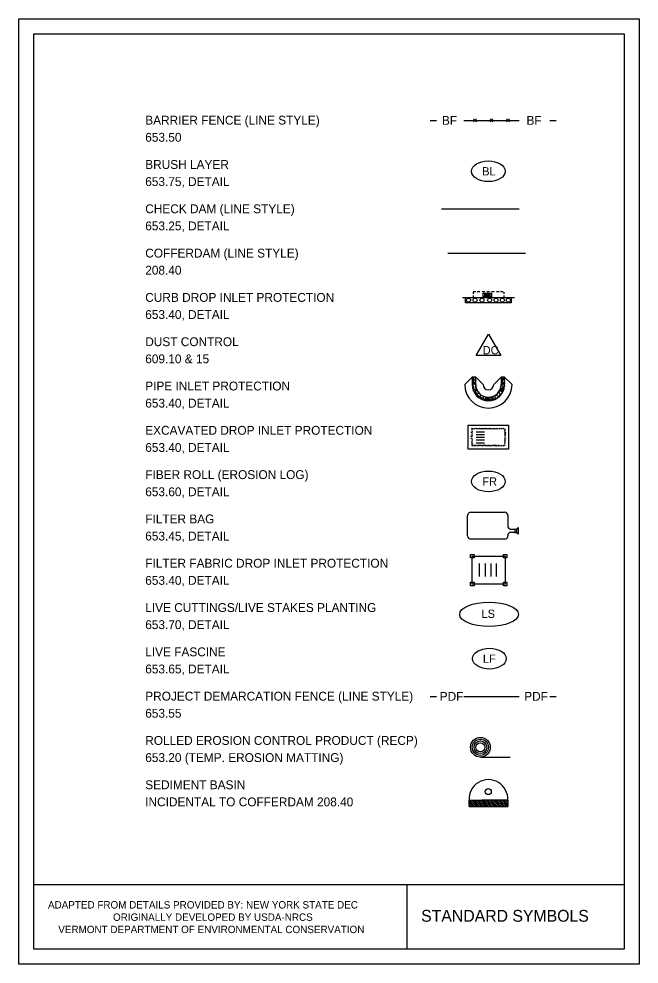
# Model space of a CAD drawing. Extents: x 0 to 556, y -320 to 0.
# Drawn here: x 0 to 210, y -320 to 0 of the extents above; entities that cross this region are included whole.
import ezdxf

# ---------------------------------------------------------------- set-up
doc = ezdxf.new("R2010")
doc.units = 0
for name, color, linetype in [('Default', 7, 'Continuous'), ('Level 6', 7, 'Continuous'), ('NBC1', 7, 'Continuous'), ('NBL1', 7, 'Continuous'), ('NBL1_T', 7, 'Continuous'), ('ODIM_T', 7, 'Continuous')]:
    doc.layers.add(name, color=color, linetype=linetype)

# ---------------------------------------------------------------- blocks, each defined once
blk = doc.blocks.new('UNITSQUARE')
at = {"layer": 'Default'}
for p, q in [((0.001, 0.001), (0, 0.001)), ((0, 0.001), (0, 0)), ((0, 0), (0.001, 0)), ((0.001, 0), (0.001, 0.001))]:
    blk.add_line(p, q, dxfattribs=at)
blk = doc.blocks.new('A$C052A225E')
at = {"layer": 'Default'}
for p, q in [((0.00443, 0.00472), (0.00552, 0.00472)), ((0.00445, 0.00437), (0.00445, 0.00368)), ((0.0061, 0.00472), (0.00718, 0.00472)), ((0.00814, 0.00472), (0.00922, 0.00472)), ((0.0101, 0.00472), (0.01119, 0.00472)), ((0.01207, 0.00472), (0.01315, 0.00472)), ((0.01418, 0.00472), (0.01527, 0.00472)), ((0.01584, 0.00472), (0.01693, 0.00472)), ((0.01723, 0.00435), (0.01723, 0.00366)), ((0, 0.00221), (0.0216, 0.00221)), ((0.00128, 0), (0.00128, 0.00221)), ((0.00445, 0.00303), (0.00445, 0.00234)), ((0.01723, 0.00299), (0.01723, 0.0023)), ((0.02025, 0.00221), (0.02025, 0)), ((0.02025, 0), (0.00128, 0))]:
    blk.add_line(p, q, dxfattribs=at)
for centre in [(0.00249, 0.00107), (0.0052, 0.00107), (0.00813, 0.00107), (0.01126, 0.00107), (0.01397, 0.00107), (0.01654, 0.00107), (0.01904, 0.00107)]:
    blk.add_circle(centre, 0.000856, dxfattribs=at)
for p, xscale, yscale in [((0.00864, 0.00399), 3.35095312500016, -1.4972343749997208), ((0.00927, 0.00356), 2.1389062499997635, -0.7842656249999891), ((0.0097, 0.00328), 1.3546406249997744, -0.21389062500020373)]:
    blk.add_blockref('UNITSQUARE', p, dxfattribs=dict(at, xscale=xscale, yscale=yscale))

msp = doc.modelspace()

# ---------------------------------------------------------------- linework, layer by layer
at = {"layer": 'Level 6'}
for p, q in [((139.29, -34.36), (141.43, -34.36)), ((150.71, -34.36), (169.34, -34.36)), ((153.94, -33.86), (154.94, -34.86)), ((153.94, -34.86), (154.94, -33.86)), ((159.53, -33.86), (160.53, -34.86)), ((159.53, -34.86), (160.53, -33.86)), ((165.11, -33.86), (166.11, -34.86)), ((165.11, -34.86), (166.11, -33.86)), ((179.72, -34.36), (181.87, -34.36)), ((143.08, -64.29), (169.44, -64.29)), ((145.19, -79.29), (171.56, -79.29)), ((150.97, -123.78), (153.47, -121.28)), ((154.67, -121.28), (153.47, -121.28)), ((153.47, -121.28), (153.47, -123.78)), ((154.08, -121.78), (154.08, -121.28)), ((154.61, -121.28), (154.63, -121.48)), ((154.63, -121.48), (154.67, -121.52)), ((154.67, -121.28), (157.17, -123.78)), ((154.67, -123.78), (154.67, -121.28)), ((160.77, -123.78), (163.27, -121.28)), ((164.47, -121.28), (163.27, -121.28)), ((163.27, -121.28), (163.27, -123.78)), ((163.92, -121.78), (163.92, -121.28)), ((164.45, -121.28), (164.47, -121.48)), ((164.47, -121.28), (166.97, -123.78)), ((164.47, -123.78), (164.47, -121.28)), ((164.47, -121.48), (164.47, -121.48)), ((153.47, -121.76), (154.08, -121.78)), ((153.47, -122.17), (153.53, -122.13)), ((153.47, -122.56), (153.76, -122.53)), ((153.47, -122.81), (153.88, -123.18)), ((153.47, -123.79), (153.88, -123.81)), ((153.48, -123.96), (153.53, -123.96)), ((153.53, -122.13), (153.76, -122.53)), ((153.53, -123.96), (154.08, -124.43)), ((153.88, -123.81), (153.88, -123.18)), ((153.94, -123.08), (153.96, -122.31)), ((153.94, -123.08), (154.57, -123.08)), ((153.96, -122.31), (154.31, -121.96)), ((154.08, -125.06), (154.08, -124.43)), ((154.14, -123.55), (154.29, -123.29)), ((154.14, -123.55), (154.37, -123.81)), ((154.29, -123.29), (154.59, -123.41)), ((154.31, -121.95), (154.57, -123.08)), ((154.37, -123.81), (154.61, -123.59)), ((154.55, -124.07), (154.68, -124.06)), ((154.55, -124.08), (154.63, -124.76)), ((154.57, -122.07), (154.67, -121.98)), ((154.57, -122.07), (154.67, -122.37)), ((154.59, -123.41), (154.61, -123.59)), ((154.63, -124.76), (154.83, -124.95)), ((154.67, -122.37), (154.67, -122.37)), ((163.27, -121.76), (163.92, -121.78)), ((163.27, -122.2), (163.37, -122.13)), ((163.27, -122.51), (163.31, -122.57)), ((163.27, -122.77), (163.72, -123.18)), ((163.27, -123.79), (163.72, -123.81)), ((163.27, -123.97), (163.37, -123.96)), ((163.31, -122.57), (163.6, -122.53)), ((163.37, -122.13), (163.6, -122.53)), ((163.37, -123.96), (163.92, -124.43)), ((163.72, -123.81), (163.72, -123.18)), ((163.78, -123.08), (163.8, -122.31)), ((163.78, -123.08), (164.41, -123.08)), ((163.8, -122.31), (164.16, -121.96)), ((163.92, -125.06), (163.92, -124.43)), ((163.98, -123.55), (164.14, -123.29)), ((163.98, -123.55), (164.21, -123.81)), ((164.14, -123.29), (164.43, -123.41)), ((164.16, -121.96), (164.41, -123.08)), ((164.21, -123.81), (164.45, -123.59)), ((164.39, -124.07), (164.47, -124.07)), ((164.39, -124.07), (164.43, -124.44)), ((164.41, -122.07), (164.47, -122.02)), ((164.41, -122.07), (164.47, -122.26)), ((164.43, -123.41), (164.45, -123.59)), ((153.62, -125.05), (154.08, -125.06)), ((153.95, -126.02), (153.96, -125.59)), ((153.96, -125.59), (154.31, -125.24)), ((154.11, -126.36), (154.57, -126.36)), ((154.26, -126.62), (154.29, -126.57)), ((154.29, -126.57), (154.59, -126.69)), ((154.31, -125.24), (154.57, -126.36)), ((154.49, -126.97), (154.61, -126.87)), ((154.57, -125.35), (154.71, -125.24)), ((154.57, -125.35), (154.67, -125.65)), ((154.59, -126.69), (154.61, -126.87)), ((154.67, -125.65), (154.96, -125.63)), ((154.69, -126.4), (154.81, -125.91)), ((154.69, -126.4), (155.04, -127.07)), ((154.71, -125.24), (154.94, -125.28)), ((154.77, -127.33), (155.2, -127.3)), ((154.81, -125.91), (155.11, -125.67)), ((154.96, -125.63), (155, -125.43)), ((155.04, -127.07), (155.59, -126.75)), ((155.2, -127.3), (155.75, -127.77)), ((155.59, -126.75), (155.64, -126.5)), ((155.75, -127.77), (155.76, -128.25)), ((156.14, -127.3), (156.45, -127.27)), ((156.14, -127.3), (156.24, -127.99)), ((156.24, -127.99), (156.61, -128.32)), ((157.36, -128.34), (157.36, -127.77)), ((157.9, -127.95), (157.91, -128.04)), ((160.64, -128.34), (160.64, -127.75)), ((161.13, -127.5), (161.19, -128.04)), ((161.41, -127.33), (161.76, -127.3)), ((161.76, -127.3), (162.31, -127.77)), ((161.99, -126.84), (162.15, -126.75)), ((162.15, -126.75), (162.17, -126.66)), ((162.31, -127.77), (162.32, -128.15)), ((162.53, -126.21), (162.6, -126.71)), ((162.6, -126.71), (162.97, -127.07)), ((162.64, -126.03), (163.17, -125.96)), ((162.7, -127.3), (163.24, -127.25)), ((162.7, -127.3), (162.77, -127.77)), ((162.89, -125.57), (162.97, -125.49)), ((162.94, -125.43), (162.97, -125.49)), ((162.97, -127.07), (163.38, -127.08)), ((163.1, -124.98), (163.17, -125.04)), ((163.17, -125.04), (163.92, -125.06)), ((163.17, -125.96), (163.72, -126.46)), ((163.21, -125.53), (163.37, -125.41)), ((163.21, -125.71), (163.21, -125.53)), ((163.21, -125.71), (163.31, -125.85)), ((163.31, -125.85), (163.6, -125.81)), ((163.37, -125.41), (163.6, -125.81)), ((163.72, -126.56), (163.72, -126.46)), ((163.78, -126.36), (163.8, -125.59)), ((163.78, -126.36), (163.83, -126.36)), ((163.8, -125.59), (164.16, -125.24)), ((164.16, -125.24), (164.21, -125.47)), ((156.17, -128.51), (156.26, -128.48)), ((156.26, -128.48), (156.32, -128.6)), ((156.61, -128.32), (157.36, -128.34)), ((156.69, -128.78), (156.81, -128.69)), ((156.81, -128.69), (156.92, -128.89)), ((157.24, -128.87), (157.59, -128.52)), ((157.24, -129), (157.24, -128.87)), ((157.59, -128.52), (157.74, -129.14)), ((157.85, -128.63), (157.99, -128.52)), ((157.85, -128.63), (157.95, -128.93)), ((157.91, -128.04), (158.28, -128.38)), ((157.95, -128.93), (158.24, -128.91)), ((157.99, -128.52), (158.3, -128.58)), ((158.08, -129.21), (158.09, -129.19)), ((158.09, -129.19), (158.62, -128.77)), ((158.24, -128.91), (158.3, -128.58)), ((158.28, -128.38), (159.05, -128.42)), ((158.62, -128.77), (159, -129.28)), ((159.04, -128.08), (159.05, -128.42)), ((159.2, -128.77), (159.26, -128.6)), ((159.2, -128.77), (159.3, -128.93)), ((159.26, -128.6), (159.54, -128.48)), ((159.3, -128.93), (159.46, -128.97)), ((159.46, -128.97), (159.69, -128.77)), ((159.54, -128.48), (159.69, -128.77)), ((159.58, -128.04), (159.89, -128.32)), ((159.89, -128.32), (160.64, -128.34)), ((159.93, -128.81), (160.09, -128.69)), ((159.93, -128.99), (159.93, -128.81)), ((159.93, -128.99), (160.03, -129.13)), ((160.03, -129.13), (160.32, -129.09)), ((160.09, -128.69), (160.32, -129.09)), ((160.52, -128.87), (160.88, -128.52)), ((160.52, -129.06), (160.52, -128.87)), ((160.88, -128.52), (160.96, -128.91)), ((161.13, -128.63), (161.27, -128.52)), ((161.13, -128.63), (161.19, -128.82)), ((161.19, -128.04), (161.56, -128.38)), ((161.27, -128.52), (161.58, -128.58)), ((161.56, -128.38), (161.96, -128.4)), ((161.57, -128.63), (161.58, -128.58)), ((153.57, -140.17), (153.03, -139.99)), ((153.57, -138.93), (153.21, -138.57)), ((153.57, -139.28), (153.21, -139.11)), ((153.57, -139.64), (153.21, -139.82)), ((153.57, -140.52), (153.21, -140.7)), ((153.74, -138.93), (153.74, -138.57)), ((154.1, -138.93), (154.28, -138.57)), ((154.63, -138.93), (154.45, -138.57)), ((154.81, -139.82), (157.64, -139.82)), ((154.81, -140.7), (157.64, -140.7)), ((154.98, -138.93), (155.16, -138.57)), ((155.52, -138.93), (155.52, -138.57)), ((156.05, -138.93), (155.87, -138.57)), ((156.4, -138.93), (156.4, -138.57)), ((156.76, -138.93), (156.93, -138.57)), ((157.29, -138.93), (157.11, -138.57)), ((157.64, -138.93), (157.47, -138.57)), ((158, -138.93), (158, -138.57)), ((158.35, -138.93), (158.53, -138.57)), ((158.88, -138.93), (158.88, -138.57)), ((159.24, -138.93), (159.42, -138.57)), ((159.59, -138.93), (159.77, -138.57)), ((160.13, -138.93), (160.3, -138.57)), ((160.66, -138.93), (160.48, -138.57)), ((161.01, -138.93), (161.01, -138.57)), ((161.37, -138.93), (161.54, -138.57)), ((161.72, -138.93), (161.9, -138.57)), ((162.25, -138.93), (162.43, -138.57)), ((162.78, -138.93), (162.96, -138.57)), ((163.32, -138.93), (163.49, -138.57)), ((163.85, -138.93), (164.03, -138.57)), ((164.2, -138.93), (164.03, -138.57)), ((164.38, -138.93), (164.56, -138.75)), ((164.38, -139.28), (164.73, -138.93)), ((164.38, -139.64), (164.73, -139.28)), ((164.38, -139.82), (164.91, -140.17)), ((164.38, -140.35), (164.91, -140.35)), ((164.56, -140.88), (164.91, -140.52)), ((153.57, -141.06), (153.03, -141.23)), ((153.57, -141.59), (153.03, -141.41)), ((153.57, -142.12), (153.03, -141.94)), ((153.57, -142.47), (153.21, -142.65)), ((153.57, -142.83), (153.21, -143.18)), ((153.57, -143.54), (153.21, -143.72)), ((153.57, -143.89), (153.21, -144.07)), ((154.81, -141.59), (157.64, -141.59)), ((154.81, -142.47), (157.64, -142.47)), ((154.81, -143.54), (157.64, -143.54)), ((164.38, -141.23), (164.91, -141.06)), ((164.38, -141.77), (164.91, -141.94)), ((164.38, -142.3), (164.73, -142.12)), ((164.38, -142.83), (164.73, -142.47)), ((164.38, -143.01), (164.73, -143.18)), ((164.38, -143.54), (164.56, -143.36)), ((164.38, -143.89), (164.73, -143.72)), ((153.57, -144.25), (153.21, -144.6)), ((153.74, -144.25), (153.74, -144.6)), ((154.1, -144.25), (154.28, -144.6)), ((154.63, -144.25), (154.45, -144.6)), ((154.98, -144.25), (155.16, -144.6)), ((155.52, -144.25), (155.52, -144.6)), ((156.05, -144.25), (155.87, -144.6)), ((156.4, -144.25), (156.4, -144.6)), ((156.76, -144.25), (156.93, -144.6)), ((157.29, -144.25), (157.11, -144.6)), ((157.64, -144.25), (157.47, -144.6)), ((158, -144.25), (158, -144.6)), ((158.35, -144.25), (158.53, -144.6)), ((158.88, -144.25), (158.88, -144.6)), ((159.24, -144.25), (159.42, -144.6)), ((159.59, -144.25), (159.77, -144.6)), ((160.13, -144.25), (160.3, -144.6)), ((160.66, -144.25), (160.48, -144.6)), ((161.01, -144.25), (161.01, -144.6)), ((161.37, -144.25), (161.54, -144.6)), ((161.72, -144.25), (161.9, -144.6)), ((162.25, -144.25), (162.43, -144.6)), ((162.78, -144.25), (162.96, -144.6)), ((163.32, -144.25), (163.49, -144.6)), ((163.85, -144.25), (164.03, -144.6)), ((164.2, -144.25), (164.03, -144.6)), ((164.38, -144.25), (164.56, -144.42)), ((165.6, -168.18), (165.6, -171.87)), ((166.45, -172.73), (168.44, -172.73)), ((167.87, -172.73), (167.87, -173.86)), ((167.87, -172.73), (168.44, -172.73)), ((168.44, -172.73), (169.01, -172.16)), ((168.44, -172.73), (168.44, -173.86)), ((169.01, -172.16), (169.01, -174.43)), ((168.44, -173.86), (166.45, -173.86)), ((167.87, -173.86), (168.44, -173.86)), ((169.01, -174.43), (168.44, -173.86)), ((155.83, -184.39), (155.83, -188.78)), ((157.91, -184.39), (157.91, -188.78)), ((159.76, -184.39), (159.76, -188.78)), ((161.61, -184.39), (161.61, -188.78)), ((139.29, -229.36), (141.43, -229.36)), ((150.71, -229.36), (169.34, -229.36)), ((179.72, -229.36), (181.87, -229.36)), ((156.26, -249.93), (166.3, -249.93)), ((152.42, -264.52), (156.79, -264.52)), ((152.42, -266.7), (152.42, -264.52)), ((152.42, -264.95), (154.17, -266.7)), ((153.56, -266.7), (152.42, -265.56)), ((154.78, -266.7), (152.6, -264.52)), ((153.21, -264.52), (155.39, -266.7)), ((156, -266.7), (153.82, -264.52)), ((154.43, -264.52), (156.61, -266.7)), ((157.22, -266.7), (155.04, -264.52)), ((155.65, -264.52), (157.84, -266.7)), ((158.45, -266.7), (156.26, -264.52)), ((161.16, -264.52), (156.79, -264.52)), ((156.87, -264.52), (159.06, -266.7)), ((159.67, -266.7), (157.48, -264.52)), ((158.1, -264.52), (160.28, -266.7)), ((160.89, -266.7), (158.71, -264.52)), ((159.32, -264.52), (161.5, -266.7)), ((162.11, -266.7), (159.93, -264.52)), ((160.54, -264.52), (162.72, -266.7)), ((163.34, -266.7), (161.15, -264.52)), ((165.53, -264.52), (161.16, -264.52)), ((161.76, -264.52), (163.95, -266.7)), ((164.56, -266.7), (162.37, -264.52)), ((162.98, -264.52), (165.17, -266.7)), ((165.53, -266.45), (163.59, -264.52)), ((164.21, -264.52), (165.53, -265.84)), ((165.53, -265.23), (164.82, -264.52)), ((165.43, -264.52), (165.53, -264.62)), ((165.53, -264.52), (165.53, -266.7)), ((152.42, -266.17), (152.95, -266.7)), ((152.42, -266.7), (156.79, -266.7)), ((156.79, -266.7), (161.16, -266.7)), ((161.16, -266.7), (165.53, -266.7))]:
    msp.add_line(p, q, dxfattribs=at)
for points in [[(154.82, -113.99), (158.97, -106.79), (163.13, -113.99)], [(152.15, -137.51), (165.8, -137.51), (165.8, -145.67), (152.15, -145.67)], [(152.95, -181.28), (154.1, -181.28), (154.1, -182.43), (152.95, -182.43)], [(153.52, -181.85), (164.61, -181.85), (164.61, -191.32), (153.52, -191.32)], [(164.03, -181.28), (165.18, -181.28), (165.18, -182.43), (164.03, -182.43)], [(152.95, -190.75), (154.1, -190.75), (154.1, -191.9), (152.95, -191.9)], [(164.03, -190.75), (165.18, -190.75), (165.18, -191.9), (164.03, -191.9)]]:
    msp.add_lwpolyline(points, close=True, dxfattribs=at)
for points in [[(151.95, -175), (151.95, -168.18)], [(153.08, -167.04), (164.46, -167.04)], [(165.6, -174.72), (165.6, -175)], [(164.46, -176.14), (153.08, -176.14)]]:
    msp.add_lwpolyline(points, dxfattribs=at)
for centre, radius in [((156.26, -246.59), 3.34), ((156.26, -246.59), 2.74), ((156.26, -246.59), 2.14), ((156.26, -246.59), 1.54), ((158.93, -261.59), 1.02)]:
    msp.add_circle(centre, radius, dxfattribs=at)
for centre, radius, start, end in [((158.97, -123.78), 8, 180, 0), ((158.97, -123.78), 5.5, 180, 0), ((158.97, -123.78), 4.3, 180, 0), ((158.97, -123.78), 1.8, 180, 0), ((153.08, -168.18), 1.14, 90, 180), ((164.46, -168.18), 1.14, 0, 90), ((166.45, -171.87), 0.853, 180, 270), ((153.08, -175), 1.14, 180, 270), ((164.46, -175), 1.14, 270, 0), ((166.45, -174.72), 0.853, 90, 180), ((158.97, -264.12), 6.57, 356.5251, 183.4749)]:
    msp.add_arc(centre, radius, start, end, dxfattribs=at)
for centre, major_axis, ratio in [((158.97, -51.59), (5.7, 0), 0.615252), ((158.97, -156.59), (5.7, 0), 0.615252), ((159.19, -201.59), (9.94, 0), 0.416263), ((159.32, -216.59), (5.7, 0), 0.615252)]:
    msp.add_ellipse(centre, major_axis=major_axis, ratio=ratio, dxfattribs=at)
at = {"layer": 'NBC1'}
msp.add_lwpolyline([(0, 0), (210, 0), (210, -320), (0, -320)], close=True, dxfattribs=at)
at = {"layer": 'NBL1'}
msp.add_line((131.4, -293.13), (131.4, -315), dxfattribs=at)
msp.add_lwpolyline([(5, -5), (205, -5), (205, -315), (5, -315)], close=True, dxfattribs=at)
msp.add_lwpolyline([(205, -293.13), (5, -293.13)], dxfattribs=at)

# ---------------------------------------------------------------- block references
at = {"layer": 'Level 6', "xscale": 814.54545, "yscale": 814.54545}
msp.add_blockref('A$C052A225E', (150.2, -96.09), dxfattribs=at)

# ---------------------------------------------------------------- texts
at = {"layer": 'Level 6'}
for s, height, p in [('BF', 3, (143.24, -35.86)), ('BF', 3, (171.87, -35.86)), ('BL', 2.8, (156.86, -52.99)), ('DC', 2.8, (157.05, -113.56)), ('FR', 2.8, (156.9, -157.99)), ('LS', 2.8, (156.63, -202.8)), ('LF', 2.8, (157.11, -217.99)), ('PDF', 3, (142.49, -230.86)), ('PDF', 3, (171.11, -230.86))]:
    msp.add_text(s, height=height, dxfattribs=at).set_placement(p)
at = {"layer": 'NBL1_T'}
for s, height, p in [('ADAPTED FROM DETAILS PROVIDED BY: NEW YORK STATE DEC', 2.5, (9.85, -301.18)), ('ORIGINALLY DEVELOPED BY USDA-NRCS', 2.5, (31.87, -305.35)), ('STANDARD SYMBOLS', 4, (136.2, -305.65)), ('VERMONT DEPARTMENT OF ENVIRONMENTAL CONSERVATION', 2.5, (13.33, -309.51))]:
    msp.add_text(s, height=height, dxfattribs=at).set_placement(p)
at = {"layer": 'ODIM_T'}
for s, p in [('BARRIER FENCE (LINE STYLE)', (42.78, -35.79)), ('653.50', (42.78, -41.59)), ('BRUSH LAYER', (42.78, -50.79)), ('653.75, DETAIL', (42.78, -56.59)), ('CHECK DAM (LINE STYLE)', (42.78, -65.79)), ('653.25, DETAIL', (42.78, -71.59)), ('COFFERDAM (LINE STYLE)', (42.78, -80.79)), ('208.40', (42.78, -86.59)), ('CURB DROP INLET PROTECTION', (42.78, -95.79)), ('653.40, DETAIL', (42.78, -101.59)), ('DUST CONTROL', (42.78, -110.79)), ('609.10 & 15', (42.78, -116.59)), ('PIPE INLET PROTECTION', (42.78, -125.79)), ('653.40, DETAIL', (42.78, -131.59)), ('EXCAVATED DROP INLET PROTECTION', (42.78, -140.79)), ('653.40, DETAIL', (42.78, -146.59)), ('FIBER ROLL (EROSION LOG)', (42.78, -155.79)), ('653.60, DETAIL', (42.78, -161.59)), ('FILTER BAG', (42.78, -170.79)), ('653.45, DETAIL', (42.78, -176.59)), ('FILTER FABRIC DROP INLET PROTECTION', (42.78, -185.79)), ('653.40, DETAIL', (42.78, -191.59)), ('LIVE CUTTINGS/LIVE STAKES PLANTING', (42.78, -200.79)), ('653.70, DETAIL', (42.78, -206.59)), ('LIVE FASCINE', (42.78, -215.79)), ('653.65, DETAIL', (42.78, -221.59)), ('PROJECT DEMARCATION FENCE (LINE STYLE)', (42.78, -230.79)), ('653.55', (42.78, -236.59)), ('ROLLED EROSION CONTROL PRODUCT (RECP)', (42.78, -245.79)), ('653.20 (TEMP. EROSION MATTING)', (42.78, -251.59)), ('SEDIMENT BASIN', (42.78, -260.79)), ('INCIDENTAL TO COFFERDAM 208.40', (42.78, -266.59))]:
    msp.add_text(s, height=3, dxfattribs=at).set_placement(p)

doc.saveas('drawing.dxf')
